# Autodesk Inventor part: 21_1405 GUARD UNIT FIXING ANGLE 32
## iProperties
Created: 2007-01
Part Number: 21_1405 GUARD UNIT FIXING ANGLE 32
Material: Steel
Document SubType Name: Modeling
Designer: Andy Moles
Density: 7.85 g/cm^3
Author: Andy Moles
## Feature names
1. Base1
